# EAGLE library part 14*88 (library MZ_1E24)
Quad 2-input NAND gate
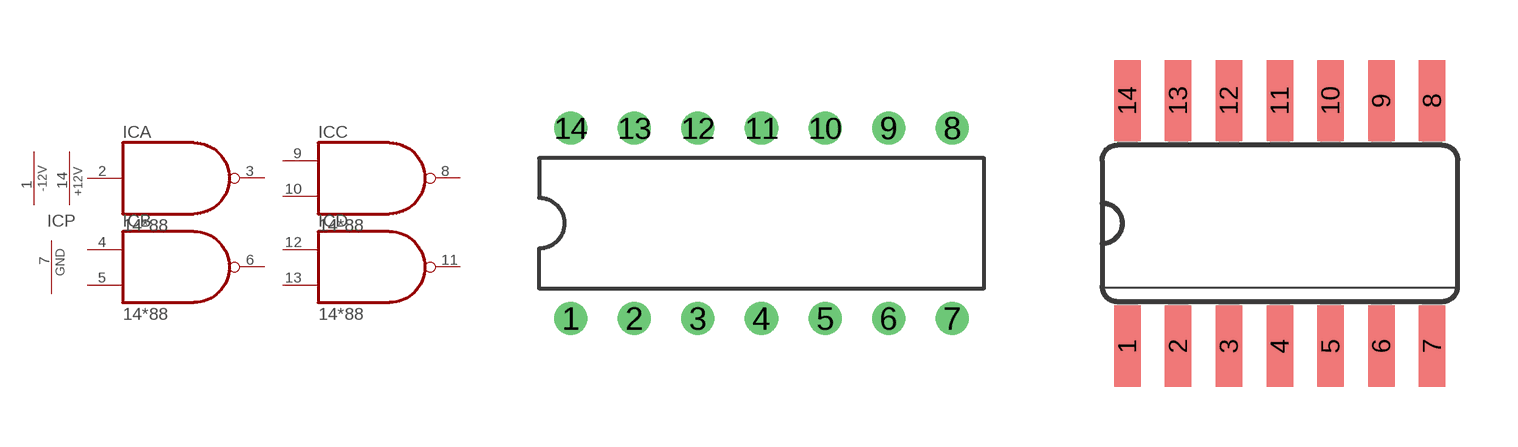
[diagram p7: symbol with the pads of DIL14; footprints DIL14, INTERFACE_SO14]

Designator prefix IC; gates A=INTERFACE_1488A B=INTERFACE_1488 C=INTERFACE_1488 D=INTERFACE_1488 P=2PWR1GND

## 1488  [DIL14]
1  P:-12V  pwr
2  A:I  in
3  A:O  out
4  B:I0  in
5  B:I1  in
6  B:O  out
7  P:GND  pwr
8  C:O  out
9  C:I0  in
10  C:I1  in
11  D:O  out
12  D:I0  in
13  D:I1  in
14  P:+12V  pwr

## 1488D, 14C88D  [INTERFACE_SO14]
Pads as for DIL14

## 1488N, 14C88N  [INTERFACE_DIL14]
Pads as for DIL14

## Footprint DIL14 (pad centres in mm)
Dual In Line Package
drill 0.813 round: 1 -7.62,-3.81; 2 -5.08,-3.81; 3 -2.54,-3.81; 4 0,-3.81; 5 2.54,-3.81; 6 5.08,-3.81; 7 7.62,-3.81; 8 7.62,3.81; 9 5.08,3.81; 10 2.54,3.81; 11 0,3.81; 12 -2.54,3.81; 13 -5.08,3.81; 14 -7.62,3.81

## Footprint INTERFACE_SO14 (pad centres in mm)
SO14 Small Outline package, 150 mil
smd 0.66 x 2.032: 1 -3.81,-3.073; 2 -2.54,-3.073; 3 -1.27,-3.073; 4 0,-3.073; 5 1.27,-3.073; 6 2.54,-3.073; 7 3.81,-3.073; 8 3.81,3.073; 9 2.54,3.073; 10 1.27,3.073; 11 0,3.073; 12 -1.27,3.073; 13 -2.54,3.073; 14 -3.81,3.073

## Footprint INTERFACE_DIL14 (pad centres in mm)
Dual In Line 14
drill 0.813 round: 1 -7.62,-3.81; 2 -5.08,-3.81; 3 -2.54,-3.81; 4 0,-3.81; 5 2.54,-3.81; 6 5.08,-3.81; 7 7.62,-3.81; 8 7.62,3.81; 9 5.08,3.81; 10 2.54,3.81; 11 0,3.81; 12 -2.54,3.81; 13 -5.08,3.81; 14 -7.62,3.81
